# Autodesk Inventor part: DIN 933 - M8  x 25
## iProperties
Created: 2005-12
Part Number: DIN 933 - M8  x 25
Material: Stahl, weich, unlegiert
Description: Sechskantschraube
Vendor: Autodesk Inc.
Document SubType Name: Modeling
Standard: DIN 933
Designer: LEIN
Standards Organization: DIN
Language: de-DE
Size Designation: M8  x 25
Categories: <MemberInstance Version="R10.0.0"><Categories><Category DisplayName="Schrauben" InternalName="e4da775c-781d-43d5-af7c-5136215cf5a6" Mnemonic="FSTN"><Category Di
Mass: 15.4764 g
Surface Area: 11.3797 cm^2
Volume: 1.96901 cm^3
Density: 7.86 g/cm^3
Author: LEIN
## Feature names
1. Körper [Revolution]
2. Kopf [Extrusion]
3. Fase1 [Revolution]
4. Fase2 [Chamfer]
